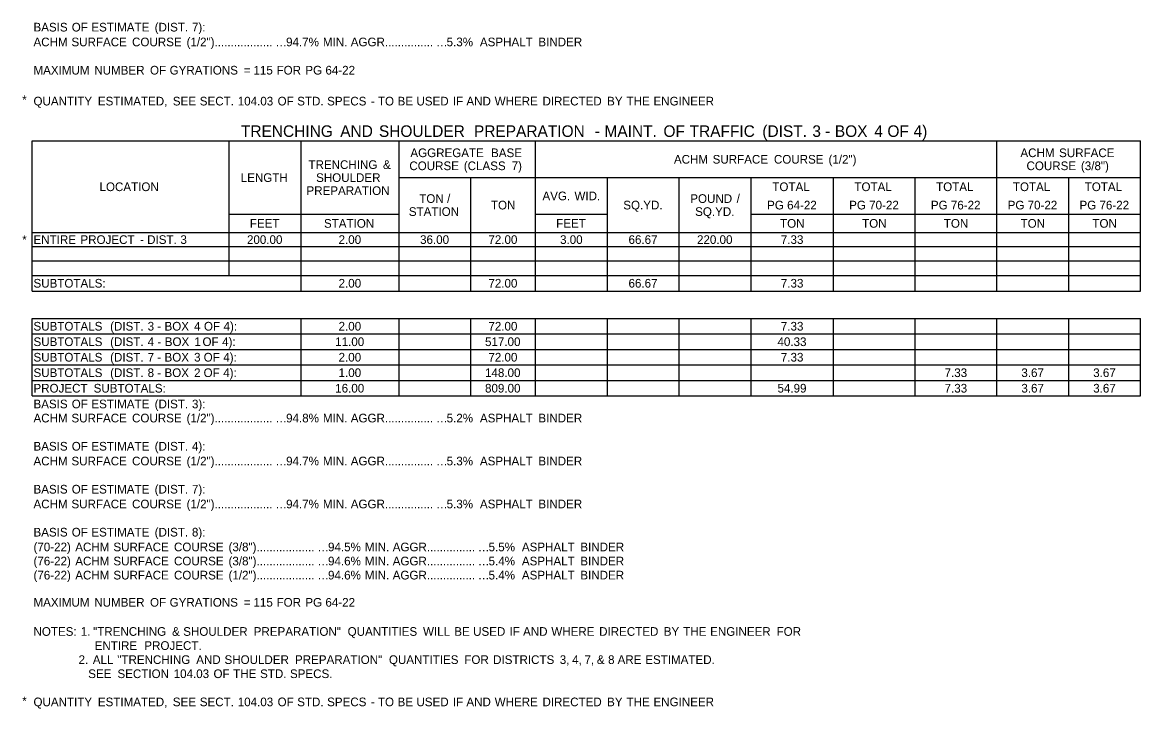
# Model space of a CAD drawing. Extents: x 540541 to 1930787, y -1948574 to 596640.
# Drawn here: x 552092 to 552866, y -1947018 to -1946543 of the extents above; entities that cross this region are included whole.
import ezdxf

# ---------------------------------------------------------------- set-up
doc = ezdxf.new("R2010")
doc.units = 0
doc.layers.add('Default', color=7, linetype='Continuous')

msp = doc.modelspace()

# ---------------------------------------------------------------- linework, layer by layer
at = {"layer": 'Default'}
for p, q in [((552098.51, -1946625.53), (552865.84, -1946625.53)), ((552098.51, -1946625.53), (552865.84, -1946625.53)), ((552098.51, -1946729.36), (552098.51, -1946625.53)), ((552098.51, -1946729.36), (552098.51, -1946625.53)), ((552235.01, -1946718.64), (552235.01, -1946625.53)), ((552284.74, -1946729.36), (552284.74, -1946625.53)), ((552352.5, -1946729.36), (552352.5, -1946625.53)), ((552447.07, -1946729.36), (552447.07, -1946625.53)), ((552766.39, -1946729.36), (552766.39, -1946625.53)), ((552865.84, -1946729.36), (552865.84, -1946625.53)), ((552352.5, -1946650.88), (552865.84, -1946650.88)), ((552402.22, -1946729.36), (552402.22, -1946650.88)), ((552496.8, -1946729.36), (552496.8, -1946650.88)), ((552546.52, -1946729.36), (552546.52, -1946650.88)), ((552596.25, -1946729.36), (552596.25, -1946650.88)), ((552653.29, -1946729.36), (552653.29, -1946650.88)), ((552709.84, -1946729.36), (552709.84, -1946650.88)), ((552816.11, -1946729.36), (552816.11, -1946650.88)), ((552235.01, -1946676.23), (552352.5, -1946676.23)), ((552284.74, -1946729.36), (552284.74, -1946676.23)), ((552447.07, -1946676.23), (552496.8, -1946676.23)), ((552447.07, -1946688.9), (552447.07, -1946676.23)), ((552496.8, -1946718.64), (552496.8, -1946676.23)), ((552596.25, -1946676.23), (552865.84, -1946676.23)), ((552098.51, -1946688.9), (552352.5, -1946688.9)), ((552235.01, -1946708.4), (552235.01, -1946688.9)), ((552352.5, -1946688.9), (552496.8, -1946688.9)), ((552352.5, -1946698.65), (552352.5, -1946688.9)), ((552402.22, -1946718.64), (552402.22, -1946688.9)), ((552496.8, -1946688.9), (552865.84, -1946688.9)), ((552546.52, -1946718.64), (552546.52, -1946688.9)), ((552098.51, -1946698.65), (552865.84, -1946698.65)), ((552098.51, -1946708.4), (552865.84, -1946708.4)), ((552352.5, -1946729.36), (552352.5, -1946708.4)), ((552098.51, -1946718.64), (552865.84, -1946718.64)), ((552235.01, -1946718.64), (552865.84, -1946718.64)), ((552596.25, -1946729.36), (552596.25, -1946718.64)), ((552098.51, -1946729.36), (552865.84, -1946729.36)), ((552098.51, -1946748.38), (552653.29, -1946748.38)), ((552098.51, -1946748.38), (552865.84, -1946748.38)), ((552098.51, -1946802), (552098.51, -1946748.38)), ((552098.51, -1946802), (552098.51, -1946748.38)), ((552284.74, -1946802), (552284.74, -1946748.38)), ((552284.74, -1946802), (552284.74, -1946748.38)), ((552352.5, -1946802), (552352.5, -1946748.38)), ((552352.5, -1946802), (552352.5, -1946748.38)), ((552402.22, -1946802), (552402.22, -1946748.38)), ((552447.07, -1946802), (552447.07, -1946748.38)), ((552496.8, -1946802), (552496.8, -1946748.38)), ((552546.52, -1946802), (552546.52, -1946748.38)), ((552596.25, -1946802), (552596.25, -1946748.38)), ((552596.25, -1946802), (552596.25, -1946748.38)), ((552653.29, -1946802), (552653.29, -1946748.38)), ((552709.84, -1946802), (552709.84, -1946748.38)), ((552766.39, -1946802), (552766.39, -1946748.38)), ((552816.11, -1946802), (552816.11, -1946748.38)), ((552865.84, -1946802), (552865.84, -1946748.38)), ((552098.51, -1946759.1), (552447.07, -1946759.1)), ((552447.07, -1946759.1), (552596.25, -1946759.1)), ((552596.25, -1946759.1), (552865.84, -1946759.1)), ((552098.51, -1946769.83), (552447.07, -1946769.83)), ((552447.07, -1946769.83), (552596.25, -1946769.83)), ((552596.25, -1946769.83), (552865.84, -1946769.83)), ((552098.51, -1946780.55), (552447.07, -1946780.55)), ((552447.07, -1946780.55), (552596.25, -1946780.55)), ((552447.07, -1946780.55), (552596.25, -1946780.55)), ((552596.25, -1946780.55), (552865.84, -1946780.55)), ((552098.51, -1946791.28), (552447.07, -1946791.28)), ((552447.07, -1946791.28), (552596.25, -1946791.28)), ((552447.07, -1946791.28), (552596.25, -1946791.28)), ((552596.25, -1946791.28), (552865.84, -1946791.28)), ((552098.51, -1946802), (552865.84, -1946802))]:
    msp.add_line(p, q, dxfattribs=at)

# ---------------------------------------------------------------- texts
for s, height, p in [('BASIS', 6, (552099.49, -1946549.74)), (' OF', 6, (552123.75, -1946549.74)), (' ESTIMATE', 6, (552137.33, -1946549.74)), (' (DIST.', 6, (552181.14, -1946549.74)), (' 7):', 6, (552206.95, -1946549.74)), ('ACHM', 6, (552099.49, -1946559.98)), (' SURFACE', 6, (552123.54, -1946559.98)), (' COURSE', 6, (552165.49, -1946559.98)), (' (1/2")..................', 6, (552203.24, -1946559.98)), ('…', 6, (552266.94, -1946559.98)), ('94.7%', 6, (552274.34, -1946559.98)), (' MIN.', 6, (552297.58, -1946559.98)), (' AGGR...............', 6, (552316.87, -1946559.98)), ('…', 6, (552378.07, -1946559.98)), ('5.3%', 6, (552385.47, -1946559.98)), ('  ASPHALT', 6, (552404.05, -1946559.98)), (' BINDER', 6, (552446.75, -1946559.98)), ('MAXIMUM', 6, (552099.49, -1946579.53)), (' NUMBER', 6, (552139.37, -1946579.53)), (' OF', 6, (552177.92, -1946579.53)), (' GYRATIONS', 6, (552191.51, -1946579.53)), (' =', 6, (552242.78, -1946579.53)), (' 115', 6, (552249.53, -1946579.53)), (' FOR', 6, (552265.51, -1946579.53)), (' PG', 6, (552285.42, -1946579.53)), (' 64-22', 6, (552299.33, -1946579.53)), ('*', 6, (552091.67, -1946600.01)), ('QUANTITY', 6, (552099.49, -1946600.93)), (' ESTIMATED,', 6, (552141.81, -1946600.93)), (' SEE', 6, (552193.7, -1946600.93)), (' SECT.', 6, (552212.36, -1946600.93)), (' 104.03', 6, (552238.65, -1946600.93)), (' OF', 6, (552266.23, -1946600.93)), (' STD.', 6, (552279.81, -1946600.93)), (' SPECS', 6, (552300.51, -1946600.93)), (' -', 6, (552330.82, -1946600.93)), (' TO', 6, (552335.68, -1946600.93)), (' BE', 6, (552349.27, -1946600.93)), (' USED', 6, (552362.34, -1946600.93)), (' IF', 6, (552387.51, -1946600.93)), (' AND', 6, (552396.91, -1946600.93)), (' WHERE', 6, (552416.49, -1946600.93)), (' DIRECTED', 6, (552449.58, -1946600.93)), (' BY', 6, (552494.31, -1946600.93)), (' THE', 6, (552507.76, -1946600.93)), (' ENGINEER', 6, (552526.41, -1946600.93)), ('TRENCHING', 8, (552243.09, -1946622.7)), (' AND', 8, (552308.86, -1946622.7)), (' SHOULDER', 8, (552335.63, -1946622.7)), (' PREPARATION', 8, (552401.41, -1946622.7)), (' MAINT.', 8, (552491.73, -1946622.7)), (' OF', 8, (552532.56, -1946622.7)), (' TRAFFIC', 8, (552550.67, -1946622.7)), (' (DIST.', 8, (552601.01, -1946622.7)), (' 3', 8, (552635.63, -1946622.7)), (' BOX', 8, (552651.21, -1946622.7)), (' 4', 8, (552678.53, -1946622.7)), (' OF', 8, (552687.59, -1946622.7)), (' 4)', 8, (552705.7, -1946622.7)), (' -', 8, (552484.99, -1946622.7)), (' -', 8, (552644.47, -1946622.7)), ('AGGREGATE', 6, (552360.37, -1946636.7)), (' BASE', 6, (552413.99, -1946636.7)), ('ACHM', 6, (552782.62, -1946636.7)), (' SURFACE', 6, (552807.17, -1946636.7)), ('ACHM', 6, (552542.8, -1946641.2)), (' SURFACE', 6, (552567.35, -1946641.2)), (' COURSE', 6, (552609.79, -1946641.2)), (' (1/2")', 6, (552647.57, -1946641.2)), ('TRENCHING', 6, (552289.83, -1946644.88)), (' &', 6, (552339.16, -1946644.88)), ('COURSE', 6, (552359.66, -1946645.7)), (' (CLASS', 6, (552395.12, -1946645.7)), (' 7)', 6, (552428.24, -1946645.7)), ('COURSE', 6, (552786.84, -1946645.7)), (' (3/8")', 6, (552822.29, -1946645.7)), ('LOCATION', 6, (552145.21, -1946660.21)), ('LENGTH', 6, (552242.96, -1946653.88)), ('SHOULDER', 6, (552295.11, -1946653.88)), ('TOTAL', 6, (552610.92, -1946660.21)), ('TOTAL', 6, (552667.72, -1946660.21)), ('TOTAL', 6, (552724.27, -1946660.21)), ('TOTAL', 6, (552777.4, -1946660.21)), ('TOTAL', 6, (552827.13, -1946660.21)), ('PREPARATION', 6, (552288.44, -1946662.88)), ('AVG.', 6, (552451.79, -1946666.55)), (' WID.', 6, (552471.71, -1946666.55)), ('TON', 6, (552366.52, -1946668.39)), (' /', 6, (552383.54, -1946668.39)), ('TON', 6, (552416.14, -1946672.89)), ('SQ.YD.', 6, (552507.74, -1946672.89)), ('POUND', 6, (552554.12, -1946668.39)), (' /', 6, (552583.99, -1946668.39)), ('PG', 6, (552607.3, -1946672.89)), (' 64-22', 6, (552618.9, -1946672.89)), ('PG', 6, (552664.09, -1946672.89)), (' 70-22', 6, (552675.7, -1946672.89)), ('PG', 6, (552720.64, -1946672.89)), (' 76-22', 6, (552732.25, -1946672.89)), ('PG', 6, (552773.78, -1946672.89)), (' 70-22', 6, (552785.38, -1946672.89)), ('PG', 6, (552823.5, -1946672.89)), (' 76-22', 6, (552835.11, -1946672.89)), ('STATION', 6, (552359.3, -1946677.39)), ('SQ.YD.', 6, (552557.47, -1946677.39)), ('FEET', 6, (552249.25, -1946685.56)), ('STATION', 6, (552300.56, -1946685.56)), ('FEET', 6, (552461.31, -1946685.56)), ('TON', 6, (552616.26, -1946685.56)), ('TON', 6, (552673.05, -1946685.56)), ('TON', 6, (552729.6, -1946685.56)), ('TON', 6, (552782.74, -1946685.56)), ('TON', 6, (552832.46, -1946685.56)), ('*', 6, (552091.67, -1946696.78)), ('ENTIRE', 6, (552099.49, -1946696.78)), (' PROJECT', 6, (552129.78, -1946696.78)), (' DIST.', 6, (552175.93, -1946696.78)), (' 3', 6, (552198.95, -1946696.78)), ('200.00', 6, (552247.26, -1946696.78)), ('2.00', 6, (552310.67, -1946696.78)), ('36.00', 6, (552367.08, -1946696.78)), ('72.00', 6, (552414.37, -1946696.78)), ('3.00', 6, (552463.98, -1946696.78)), ('66.67', 6, (552511.37, -1946696.78)), ('220.00', 6, (552558.77, -1946696.78)), ('7.33', 6, (552616.8, -1946696.78)), (' -', 6, (552171.08, -1946696.78)), ('SUBTOTALS:', 6, (552099.49, -1946727)), ('2.00', 6, (552310.67, -1946727)), ('72.00', 6, (552414.37, -1946727)), ('66.67', 6, (552511.36, -1946727)), ('7.33', 6, (552616.8, -1946727)), ('SUBTOTALS', 6, (552099.49, -1946756.74)), (' (DIST.', 6, (552150.31, -1946756.74)), (' 3', 6, (552176.28, -1946756.74)), (' -', 6, (552182.91, -1946756.74)), (' BOX', 6, (552187.96, -1946756.74)), (' 4', 6, (552208.45, -1946756.74)), (' OF', 6, (552215.25, -1946756.74)), (' 4):', 6, (552228.83, -1946756.74)), ('2.00', 6, (552310.67, -1946756.74)), ('72.00', 6, (552414.37, -1946756.74)), ('7.33', 6, (552616.8, -1946756.74)), ('SUBTOTALS', 6, (552099.49, -1946767.46)), (' (DIST.', 6, (552150.31, -1946767.46)), (' 4', 6, (552176.28, -1946767.46)), (' BOX', 6, (552188.13, -1946767.46)), (' 1', 6, (552208.62, -1946767.46)), (' OF', 6, (552214.25, -1946767.46)), (' 4):', 6, (552227.83, -1946767.46)), ('11.00', 6, (552308.34, -1946767.46)), ('517.00', 6, (552412.04, -1946767.46)), ('40.33', 6, (552614.47, -1946767.46)), (' -', 6, (552183.08, -1946767.46)), ('SUBTOTALS', 6, (552099.49, -1946778.19)), (' (DIST.', 6, (552150.31, -1946778.19)), (' 7', 6, (552176.28, -1946778.19)), (' -', 6, (552182.9, -1946778.19)), (' BOX', 6, (552187.96, -1946778.19)), (' 3', 6, (552208.44, -1946778.19)), (' OF', 6, (552215.07, -1946778.19)), (' 4):', 6, (552228.65, -1946778.19)), ('2.00', 6, (552310.67, -1946778.19)), ('72.00', 6, (552414.37, -1946778.19)), ('7.33', 6, (552616.8, -1946778.19)), ('SUBTOTALS', 6, (552099.49, -1946788.91)), (' (DIST.', 6, (552150.31, -1946788.91)), (' 8', 6, (552176.28, -1946788.91)), (' BOX', 6, (552187.95, -1946788.91)), (' 2', 6, (552208.44, -1946788.91)), (' OF', 6, (552215.01, -1946788.91)), (' 4):', 6, (552228.59, -1946788.91)), ('1.00', 6, (552310.67, -1946788.91)), ('148.00', 6, (552412.04, -1946788.91)), ('7.33', 6, (552730.14, -1946788.91)), ('3.67', 6, (552783.28, -1946788.91)), ('3.67', 6, (552833.01, -1946788.91)), ('PROJECT', 6, (552099.49, -1946799.64)), (' SUBTOTALS:', 6, (552138.91, -1946799.64)), (' -', 6, (552182.89, -1946788.91)), ('16.00', 6, (552308.34, -1946799.64)), ('809.00', 6, (552412.04, -1946799.64)), ('54.99', 6, (552614.48, -1946799.64)), ('7.33', 6, (552730.14, -1946799.64)), ('3.67', 6, (552783.28, -1946799.64)), ('3.67', 6, (552833.01, -1946799.64)), ('BASIS', 6, (552099.49, -1946810.55)), (' OF', 6, (552123.75, -1946810.55)), (' ESTIMATE', 6, (552137.33, -1946810.55)), (' (DIST.', 6, (552181.14, -1946810.55)), (' 3):', 6, (552206.95, -1946810.55)), ('ACHM', 6, (552099.49, -1946820.3)), (' SURFACE', 6, (552123.54, -1946820.3)), (' COURSE', 6, (552165.49, -1946820.3)), (' (1/2")..................', 6, (552203.24, -1946820.3)), ('94.8%', 6, (552274.34, -1946820.3)), (' MIN.', 6, (552297.58, -1946820.3)), (' AGGR...............', 6, (552316.87, -1946820.3)), ('5.2%', 6, (552385.47, -1946820.3)), ('  ASPHALT', 6, (552404.05, -1946820.3)), (' BINDER', 6, (552446.75, -1946820.3)), ('…', 6, (552266.94, -1946820.3)), ('…', 6, (552378.07, -1946820.3)), ('BASIS', 6, (552099.49, -1946839.8)), (' OF', 6, (552123.75, -1946839.8)), (' ESTIMATE', 6, (552137.33, -1946839.8)), (' (DIST.', 6, (552181.14, -1946839.8)), (' 4):', 6, (552206.95, -1946839.8)), ('ACHM', 6, (552099.49, -1946850.04)), (' SURFACE', 6, (552123.54, -1946850.04)), (' COURSE', 6, (552165.49, -1946850.04)), (' (1/2")..................', 6, (552203.24, -1946850.04)), ('94.7%', 6, (552274.34, -1946850.04)), (' MIN.', 6, (552297.58, -1946850.04)), (' AGGR...............', 6, (552316.87, -1946850.04)), ('5.3%', 6, (552385.47, -1946850.04)), ('  ASPHALT', 6, (552404.05, -1946850.04)), (' BINDER', 6, (552446.75, -1946850.04)), ('…', 6, (552266.94, -1946850.04)), ('…', 6, (552378.07, -1946850.04)), (' (DIST.', 6, (552181.14, -1946869.54)), (' 7):', 6, (552206.95, -1946869.54)), ('BASIS', 6, (552099.49, -1946869.54)), (' OF', 6, (552123.75, -1946869.54)), (' ESTIMATE', 6, (552137.33, -1946869.54)), ('ACHM', 6, (552099.49, -1946879.78)), (' SURFACE', 6, (552123.54, -1946879.78)), (' COURSE', 6, (552165.49, -1946879.78)), (' (1/2")..................', 6, (552203.24, -1946879.78)), ('94.7%', 6, (552274.34, -1946879.78)), (' MIN.', 6, (552297.58, -1946879.78)), (' AGGR...............', 6, (552316.87, -1946879.78)), ('5.3%', 6, (552385.47, -1946879.78)), ('  ASPHALT', 6, (552404.05, -1946879.78)), (' BINDER', 6, (552446.75, -1946879.78)), ('…', 6, (552266.94, -1946879.78)), ('…', 6, (552378.07, -1946879.78)), ('BASIS', 6, (552099.49, -1946899.28)), (' OF', 6, (552123.75, -1946899.28)), (' ESTIMATE', 6, (552137.33, -1946899.28)), (' (DIST.', 6, (552181.14, -1946899.28)), (' 8):', 6, (552206.95, -1946899.28)), ('(70-22)', 6, (552099.49, -1946909.51)), (' ACHM', 6, (552126.19, -1946909.51)), (' SURFACE', 6, (552152.58, -1946909.51)), (' COURSE', 6, (552194.52, -1946909.51)), (' (3/8")..................', 6, (552232.27, -1946909.51)), ('…', 6, (552295.97, -1946909.51)), ('94.5%', 6, (552303.37, -1946909.51)), (' MIN.', 6, (552326.61, -1946909.51)), (' AGGR...............', 6, (552345.9, -1946909.51)), ('…', 6, (552407.11, -1946909.51)), ('5.5%', 6, (552414.51, -1946909.51)), ('  ASPHALT', 6, (552433.09, -1946909.51)), (' BINDER', 6, (552475.78, -1946909.51)), ('(76-22)', 6, (552099.49, -1946919.26)), (' ACHM', 6, (552126.19, -1946919.26)), (' SURFACE', 6, (552152.58, -1946919.26)), (' COURSE', 6, (552194.52, -1946919.26)), (' (3/8")..................', 6, (552232.27, -1946919.26)), ('94.6%', 6, (552303.37, -1946919.26)), (' MIN.', 6, (552326.61, -1946919.26)), (' AGGR...............', 6, (552345.9, -1946919.26)), ('5.4%', 6, (552414.51, -1946919.26)), ('  ASPHALT', 6, (552433.09, -1946919.26)), (' BINDER', 6, (552475.78, -1946919.26)), ('(76-22)', 6, (552099.49, -1946929.01)), (' ACHM', 6, (552126.19, -1946929.01)), (' SURFACE', 6, (552152.58, -1946929.01)), (' COURSE', 6, (552194.52, -1946929.01)), (' (1/2")..................', 6, (552232.27, -1946929.01)), ('…', 6, (552295.97, -1946919.26)), ('94.6%', 6, (552303.37, -1946929.01)), (' MIN.', 6, (552326.61, -1946929.01)), (' AGGR...............', 6, (552345.9, -1946929.01)), ('…', 6, (552407.11, -1946919.26)), ('5.4%', 6, (552414.51, -1946929.01)), ('  ASPHALT', 6, (552433.09, -1946929.01)), (' BINDER', 6, (552475.78, -1946929.01)), ('…', 6, (552295.97, -1946929.01)), ('…', 6, (552407.11, -1946929.01)), ('MAXIMUM', 6, (552099.49, -1946947.84)), (' NUMBER', 6, (552139.37, -1946947.84)), (' OF', 6, (552177.92, -1946947.84)), (' GYRATIONS', 6, (552191.51, -1946947.84)), (' =', 6, (552242.78, -1946947.84)), (' 115', 6, (552249.53, -1946947.84)), (' FOR', 6, (552265.51, -1946947.84)), (' PG', 6, (552285.42, -1946947.84)), (' 64-22', 6, (552299.33, -1946947.84)), ('NOTES:', 6, (552099.49, -1946968.01)), (' 1.', 6, (552129.97, -1946968.01)), (' "TRENCHING', 6, (552138.55, -1946968.01)), (' &', 6, (552193.17, -1946968.01)), (' SHOULDER', 6, (552200.9, -1946968.01)), (' PREPARATION"', 6, (552249.7, -1946968.01)), (' QUANTITIES', 6, (552314.71, -1946968.01)), (' WILL', 6, (552366.91, -1946968.01)), (' BE', 6, (552388.5, -1946968.01)), (' USED', 6, (552401.56, -1946968.01)), (' IF', 6, (552426.74, -1946968.01)), (' AND', 6, (552436.13, -1946968.01)), (' WHERE', 6, (552455.71, -1946968.01)), (' DIRECTED', 6, (552488.8, -1946968.01)), (' BY', 6, (552533.54, -1946968.01)), (' THE', 6, (552546.99, -1946968.01)), (' ENGINEER', 6, (552565.64, -1946968.01)), (' FOR', 6, (552611.64, -1946968.01)), ('                   ENTIRE', 6, (552099.49, -1946977.76)), (' PROJECT.', 6, (552174.01, -1946977.76)), ('              2.', 6, (552099.49, -1946987.51)), (' ALL', 6, (552138.33, -1946987.51)), (' "TRENCHING', 6, (552155.28, -1946987.51)), (' AND', 6, (552209.89, -1946987.51)), (' SHOULDER', 6, (552229.48, -1946987.51)), (' PREPARATION"', 6, (552278.28, -1946987.51)), (' QUANTITIES', 6, (552343.29, -1946987.51)), (' FOR', 6, (552395.49, -1946987.51)), (' DISTRICTS', 6, (552415.4, -1946987.51)), (' 3,', 6, (552461.54, -1946987.51)), (' 4,', 6, (552470.11, -1946987.51)), (' 7,', 6, (552478.68, -1946987.51)), (' &', 6, (552487.25, -1946987.51)), (' 8', 6, (552494.98, -1946987.51)), (' ARE', 6, (552501.59, -1946987.51)), (' ESTIMATED.', 6, (552520.71, -1946987.51)), ('                 SEE', 6, (552099.49, -1946997.26)), (' SECTION', 6, (552155.39, -1946997.26)), (' 104.03', 6, (552194.3, -1946997.26)), (' OF', 6, (552221.87, -1946997.26)), (' THE', 6, (552235.46, -1946997.26)), (' STD.', 6, (552254.11, -1946997.26)), (' SPECS.', 6, (552274.8, -1946997.26)), ('*', 6, (552091.67, -1947016.09)), ('QUANTITY', 6, (552099.49, -1947016.76)), (' ESTIMATED,', 6, (552141.81, -1947016.76)), (' SEE', 6, (552193.7, -1947016.76)), (' SECT.', 6, (552212.36, -1947016.76)), (' 104.03', 6, (552238.65, -1947016.76)), (' OF', 6, (552266.23, -1947016.76)), (' STD.', 6, (552279.81, -1947016.76)), (' SPECS', 6, (552300.51, -1947016.76)), (' -', 6, (552330.82, -1947016.76)), (' TO', 6, (552335.68, -1947016.76)), (' BE', 6, (552349.27, -1947016.76)), (' USED', 6, (552362.34, -1947016.76)), (' IF', 6, (552387.51, -1947016.76)), (' AND', 6, (552396.91, -1947016.76)), (' WHERE', 6, (552416.49, -1947016.76)), (' DIRECTED', 6, (552449.58, -1947016.76)), (' BY', 6, (552494.31, -1947016.76)), (' THE', 6, (552507.76, -1947016.76)), (' ENGINEER', 6, (552526.41, -1947016.76))]:
    msp.add_text(s, height=height, dxfattribs=at).set_placement(p)

doc.saveas('drawing.dxf')
